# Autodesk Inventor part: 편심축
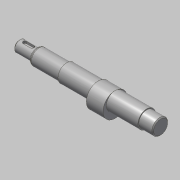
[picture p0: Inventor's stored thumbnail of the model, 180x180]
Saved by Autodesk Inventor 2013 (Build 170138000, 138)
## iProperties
Created: 2017-08
Part Number: 편심축
Material: 강철, 연강
Document SubType Name: Modeling
Designer: mduedu
Density: 1 g/cm^3
Author: mduedu
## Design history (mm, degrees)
sketch "스케치1"
  geometry: L1 (0, 0)-(152, 0); L2 (152, 0)-(152, 8.5); L3 (152, 8.5)-(137, 8.5); L4 (137, 8.5)-(137, 9.5); L5 (137, 9.5)-(51, 9.5); L6 (51, 9.5)-(51, 8.5); L7 (51, 8.5)-(19, 8.5); L8 (19, 8.5)-(19, 6); L9 (19, 6)-(0, 6); L10 (0, 6)-(0, 0)
  constraints: 20 end point, 6 parallel, 2 collinear, 2 perpendicular, 1 horizontal
  dimensions: "d0" = 152 distance of L1.start L1.end; "d1" = 17 diameter of L3 L1; "d2" = 19 diameter of L5 L1; "d3" = 12 diameter of L9 L1; "d4" = 19 distance of L8.end L9.end; "d5" = 15 distance of L2.end L3.end; "d6" = 86 distance of L4.end L5.end
revolve "회전1" sketch "스케치1" stored, may be unused: angle "d7" = 90 deg
node "작업 평면1"
sketch "스케치2"
  geometry: C1 r 9.5 at (0, 0) reference; C2 r 13 at (0, -3.5); 1 further point
  constraints: 1 centre point, 1 tangent, 1 vertical alignment
  dimensions: "d8" = 3.5 distance of point (0, 0) C2.centre
extrude "돌출1" join sketch "스케치2" stored distance "d9" = 18; taper "d10" = 0 deg
chamfer "모따기1" distance "d11" = 1; stored, may be unused: second distance "d12" = 2, angle "d13" = 45 deg
node "작업 평면2"
sketch "스케치3"
  geometry: L1 (3.5, -2)-(-4.5, -2); L2 (-4.5, -2)-(-4.5, 2); L3 (-4.5, 2)-(3.5, 2); L4 (3.5, 2)-(3.5, -2); L5 (9.5, 6)-(9.5, -6) reference; A1 r 2 centre (3.5, 0) between (3.5, -2) and (3.5, 2); A2 r 2 centre (-4.5, 0) between (-4.5, 2) and (-4.5, -2); A3 r 2 centre (3.5, 0) between (3.5, 2) and (3.5, -2); A4 r 2 centre (-4.5, 0) between (-4.5, -2) and (-4.5, 2); 1 further point
  constraints: 8 end point, 8 point on circle, 4 centre point, 2 midpoint, 2 parallel, 1 horizontal, 1 horizontal alignment, 1 perpendicular
  dimensions: "d14" = 12 dimension on A2 A1; "d16" = 4 distance between parallel lines of L3 L1; "d17" = 4 distance edge to line of A1 L5
extrude "돌출2" cut sketch "스케치3" distance "d18" = 2.5; taper "d19" = 0 deg
chamfer "모따기2" distance "d20" = 1; stored, may be unused: second distance "d21" = 2, angle "d22" = 45 deg
chamfer "모따기4" distance "d39" = 1.82; stored, may be unused: second distance "d40" = 2, angle "d41" = 30 deg
fillet "모깎기4" dims "d45" = 2
hole "구멍1" diameter "d29" = 3.242; stored, may be unused: countersink angle "d33" = 90 deg, drill point angle "d35" = 118 deg; dims "d30" = 8, "d31" = 4, "d32" = 2, "d34" = 10, "d36" = 10, "d37" = 10
node "솔리드1"
node "절단 모서리 투영1"
